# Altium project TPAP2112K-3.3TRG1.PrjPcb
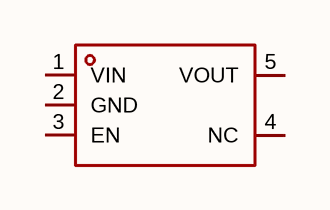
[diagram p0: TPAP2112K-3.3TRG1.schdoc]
1 sheet, 1 parts. Net scope: global (net labels, ports and power ports of the same name join across sheets).

## Sheet TPAP2112K-3.3TRG1.schdoc
size 127 x 101 mm

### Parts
U?  tpap2112k-3.3trg1  [SOT-23-5_L2.9-W1.6-P0.95-LS2.8-BR]  (value not drawn)

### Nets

Not connected (* = marked no-connect by the designer): U? 1(VIN) 2(GND) 3(EN) 4(NC) 5(VOUT)

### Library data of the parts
U? = tpap2112k-3.3trg1: 输出极性:正极;工作电压:5.5V;输出电压:3.3V;输出电流:600mA;电源纹波抑制比(PSRR):80dB@(100Hz);输出类型:固定;; Manufacturer: TECH PUBLIC(台舟); AddInBom: yes; ModelId: 7ba65df16e7b4570af156e925f9c37fe; ModelTransform: 114.173,114.173,0,90,0,0,0,0,0; Output Configuration: 正极; Voltage - Supply: 5.5V; Output Voltage: 3.3V; Output Current: 600mA; Voltage Dropout: 320mV@(600mA); standby current: 10uA; Output Type: 固定; Number of Outputs: 1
